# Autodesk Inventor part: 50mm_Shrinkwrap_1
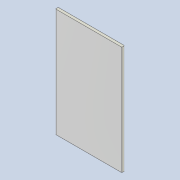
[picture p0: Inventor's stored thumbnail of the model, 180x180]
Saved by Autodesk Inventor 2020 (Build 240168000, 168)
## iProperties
Created: 2020-11
Part Number: 50mm_Shrinkwrap_1
Material: Generic
Document SubType Name: Modeling
Designer: Yolande
Density: 1 g/cm^3
Appearance: Default
description: 0:0:Lambdaboard 50mm White Mineral
manufacturer: 0:0:LambdaboardT/A Rigifoam
model: 0:0:
url: 0:0:www.lambdaboard.com
Author: Yolande
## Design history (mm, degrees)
derived "50mm.iam"
body "Solid1"
node "Lambdaboard 50mm Mineral White.ipt:1" dims "d0" = 10
